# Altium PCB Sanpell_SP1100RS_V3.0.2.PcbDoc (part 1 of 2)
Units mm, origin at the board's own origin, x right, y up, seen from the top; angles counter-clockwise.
Board outline 126.12 x 87.13 mm, 4 copper layers (TopLayer, GND, PWR, BottomLayer); 152 components, 95 nets, 511 pads, 171 vias.
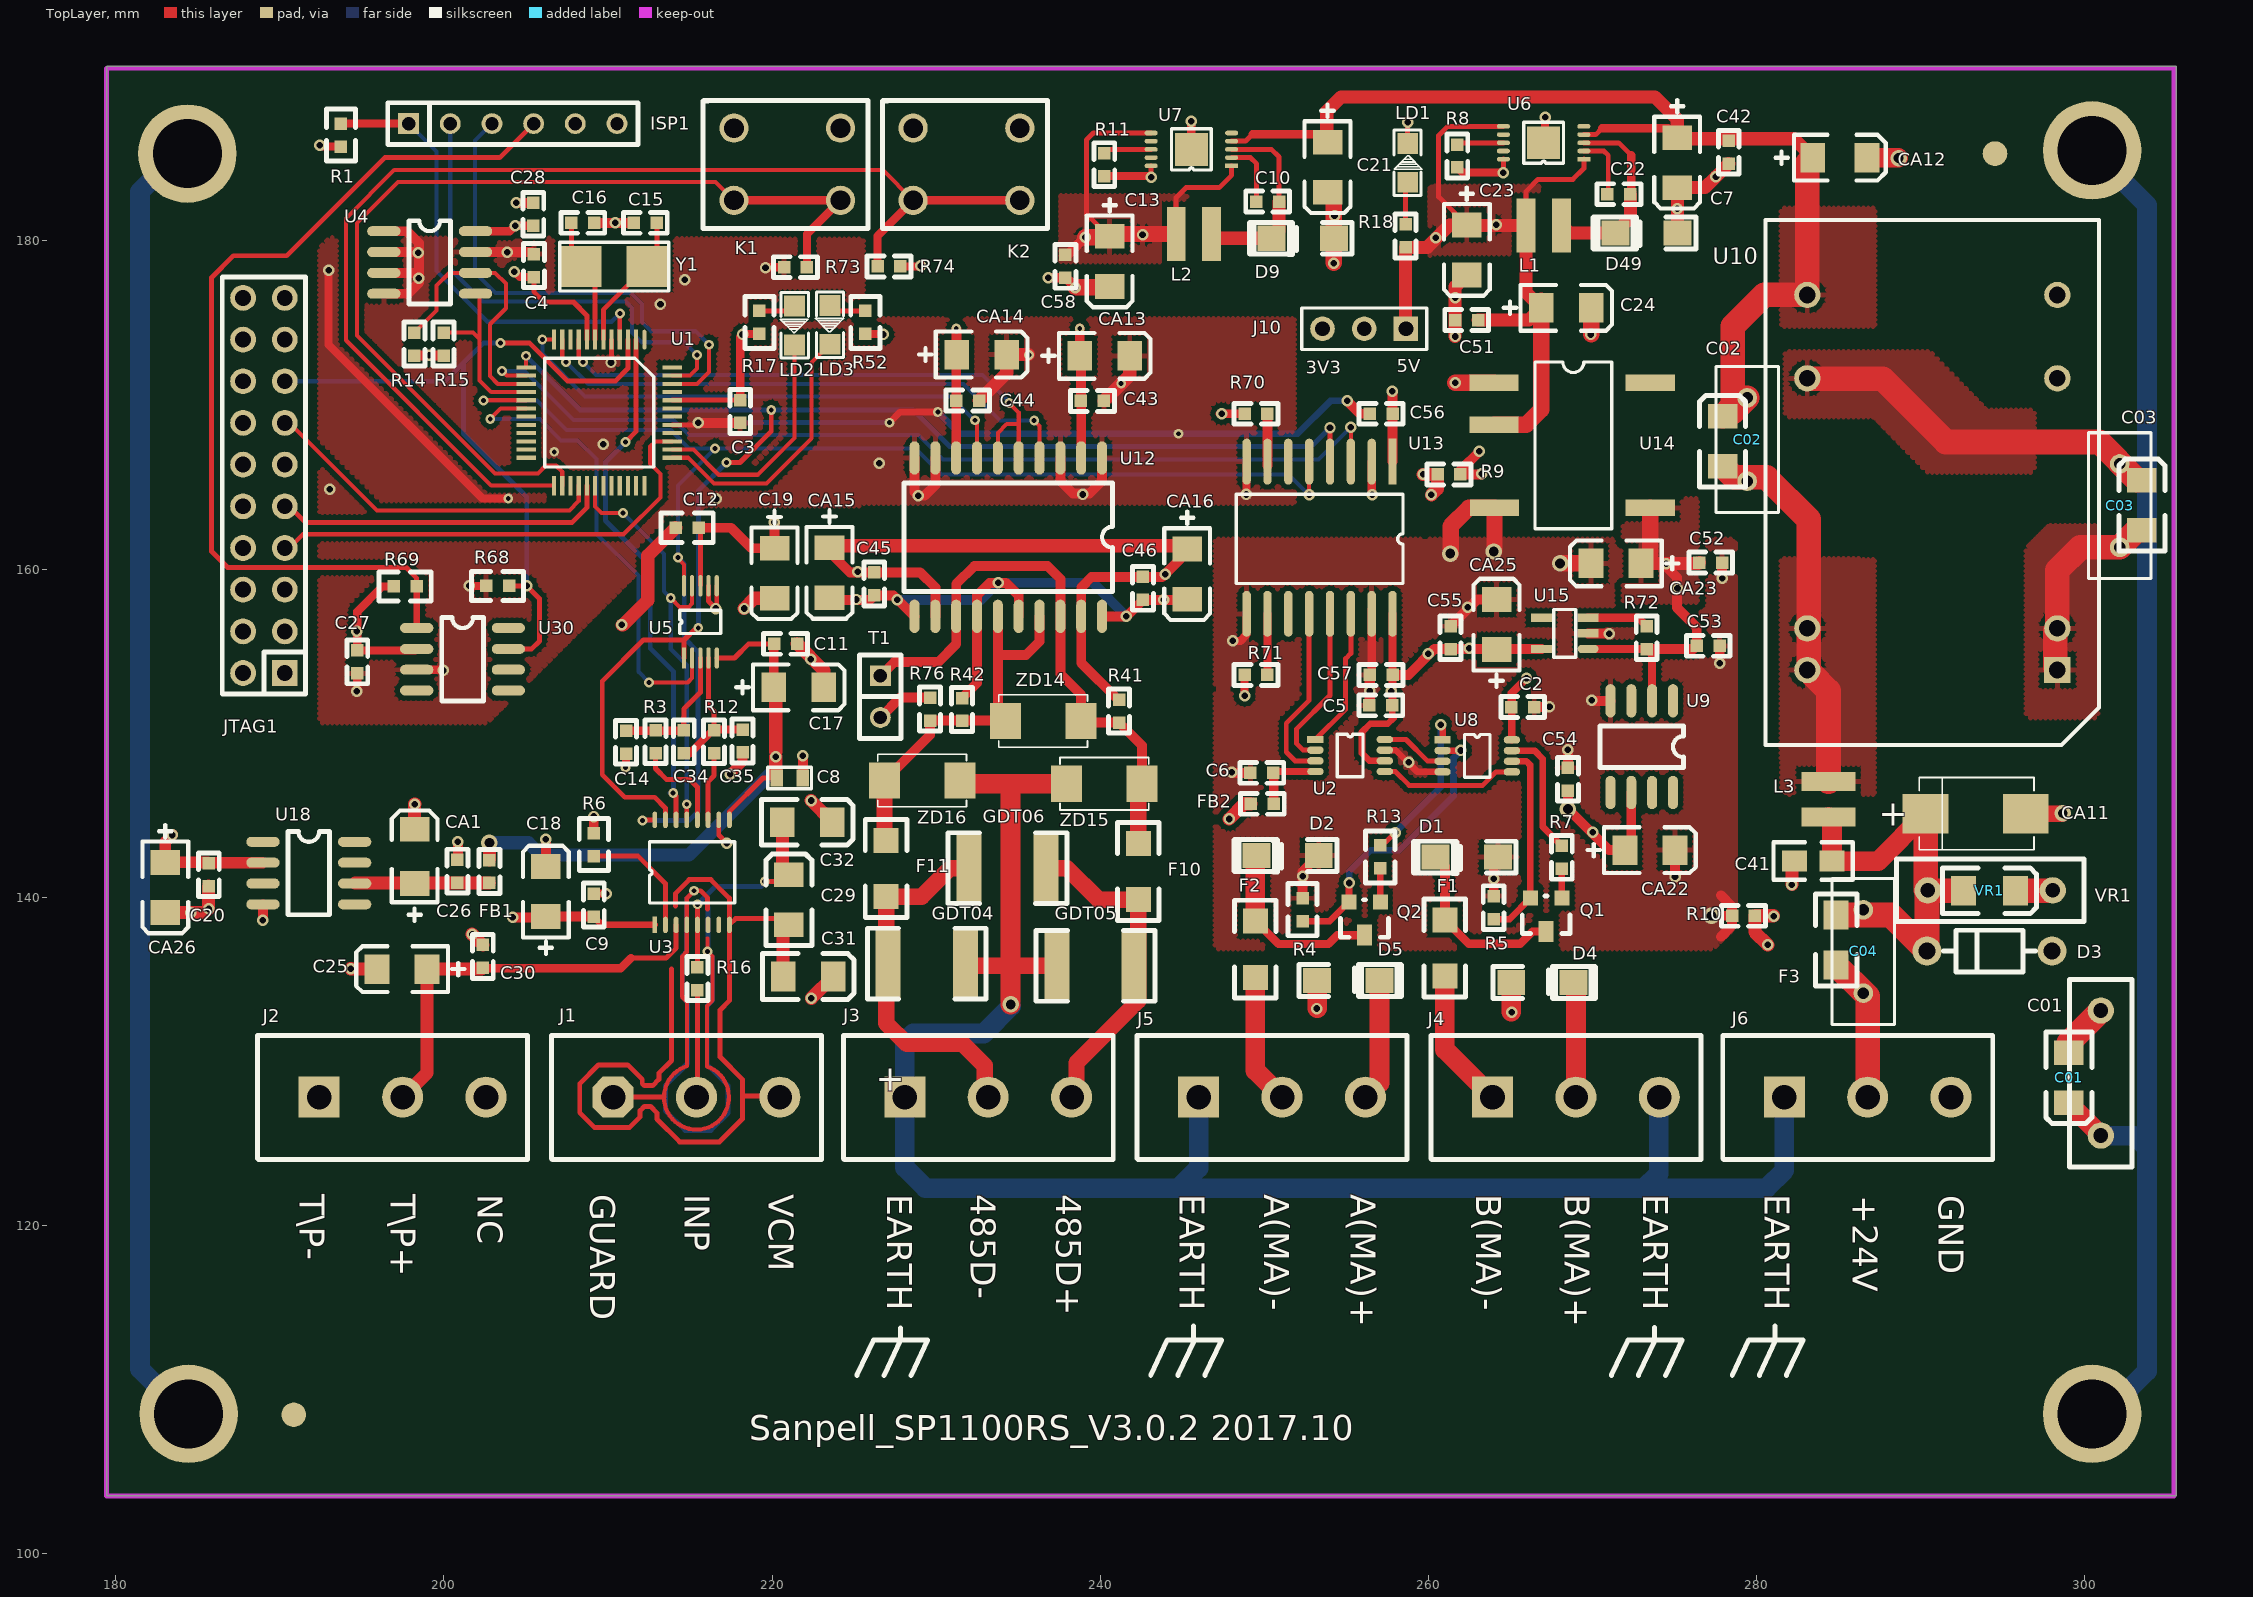
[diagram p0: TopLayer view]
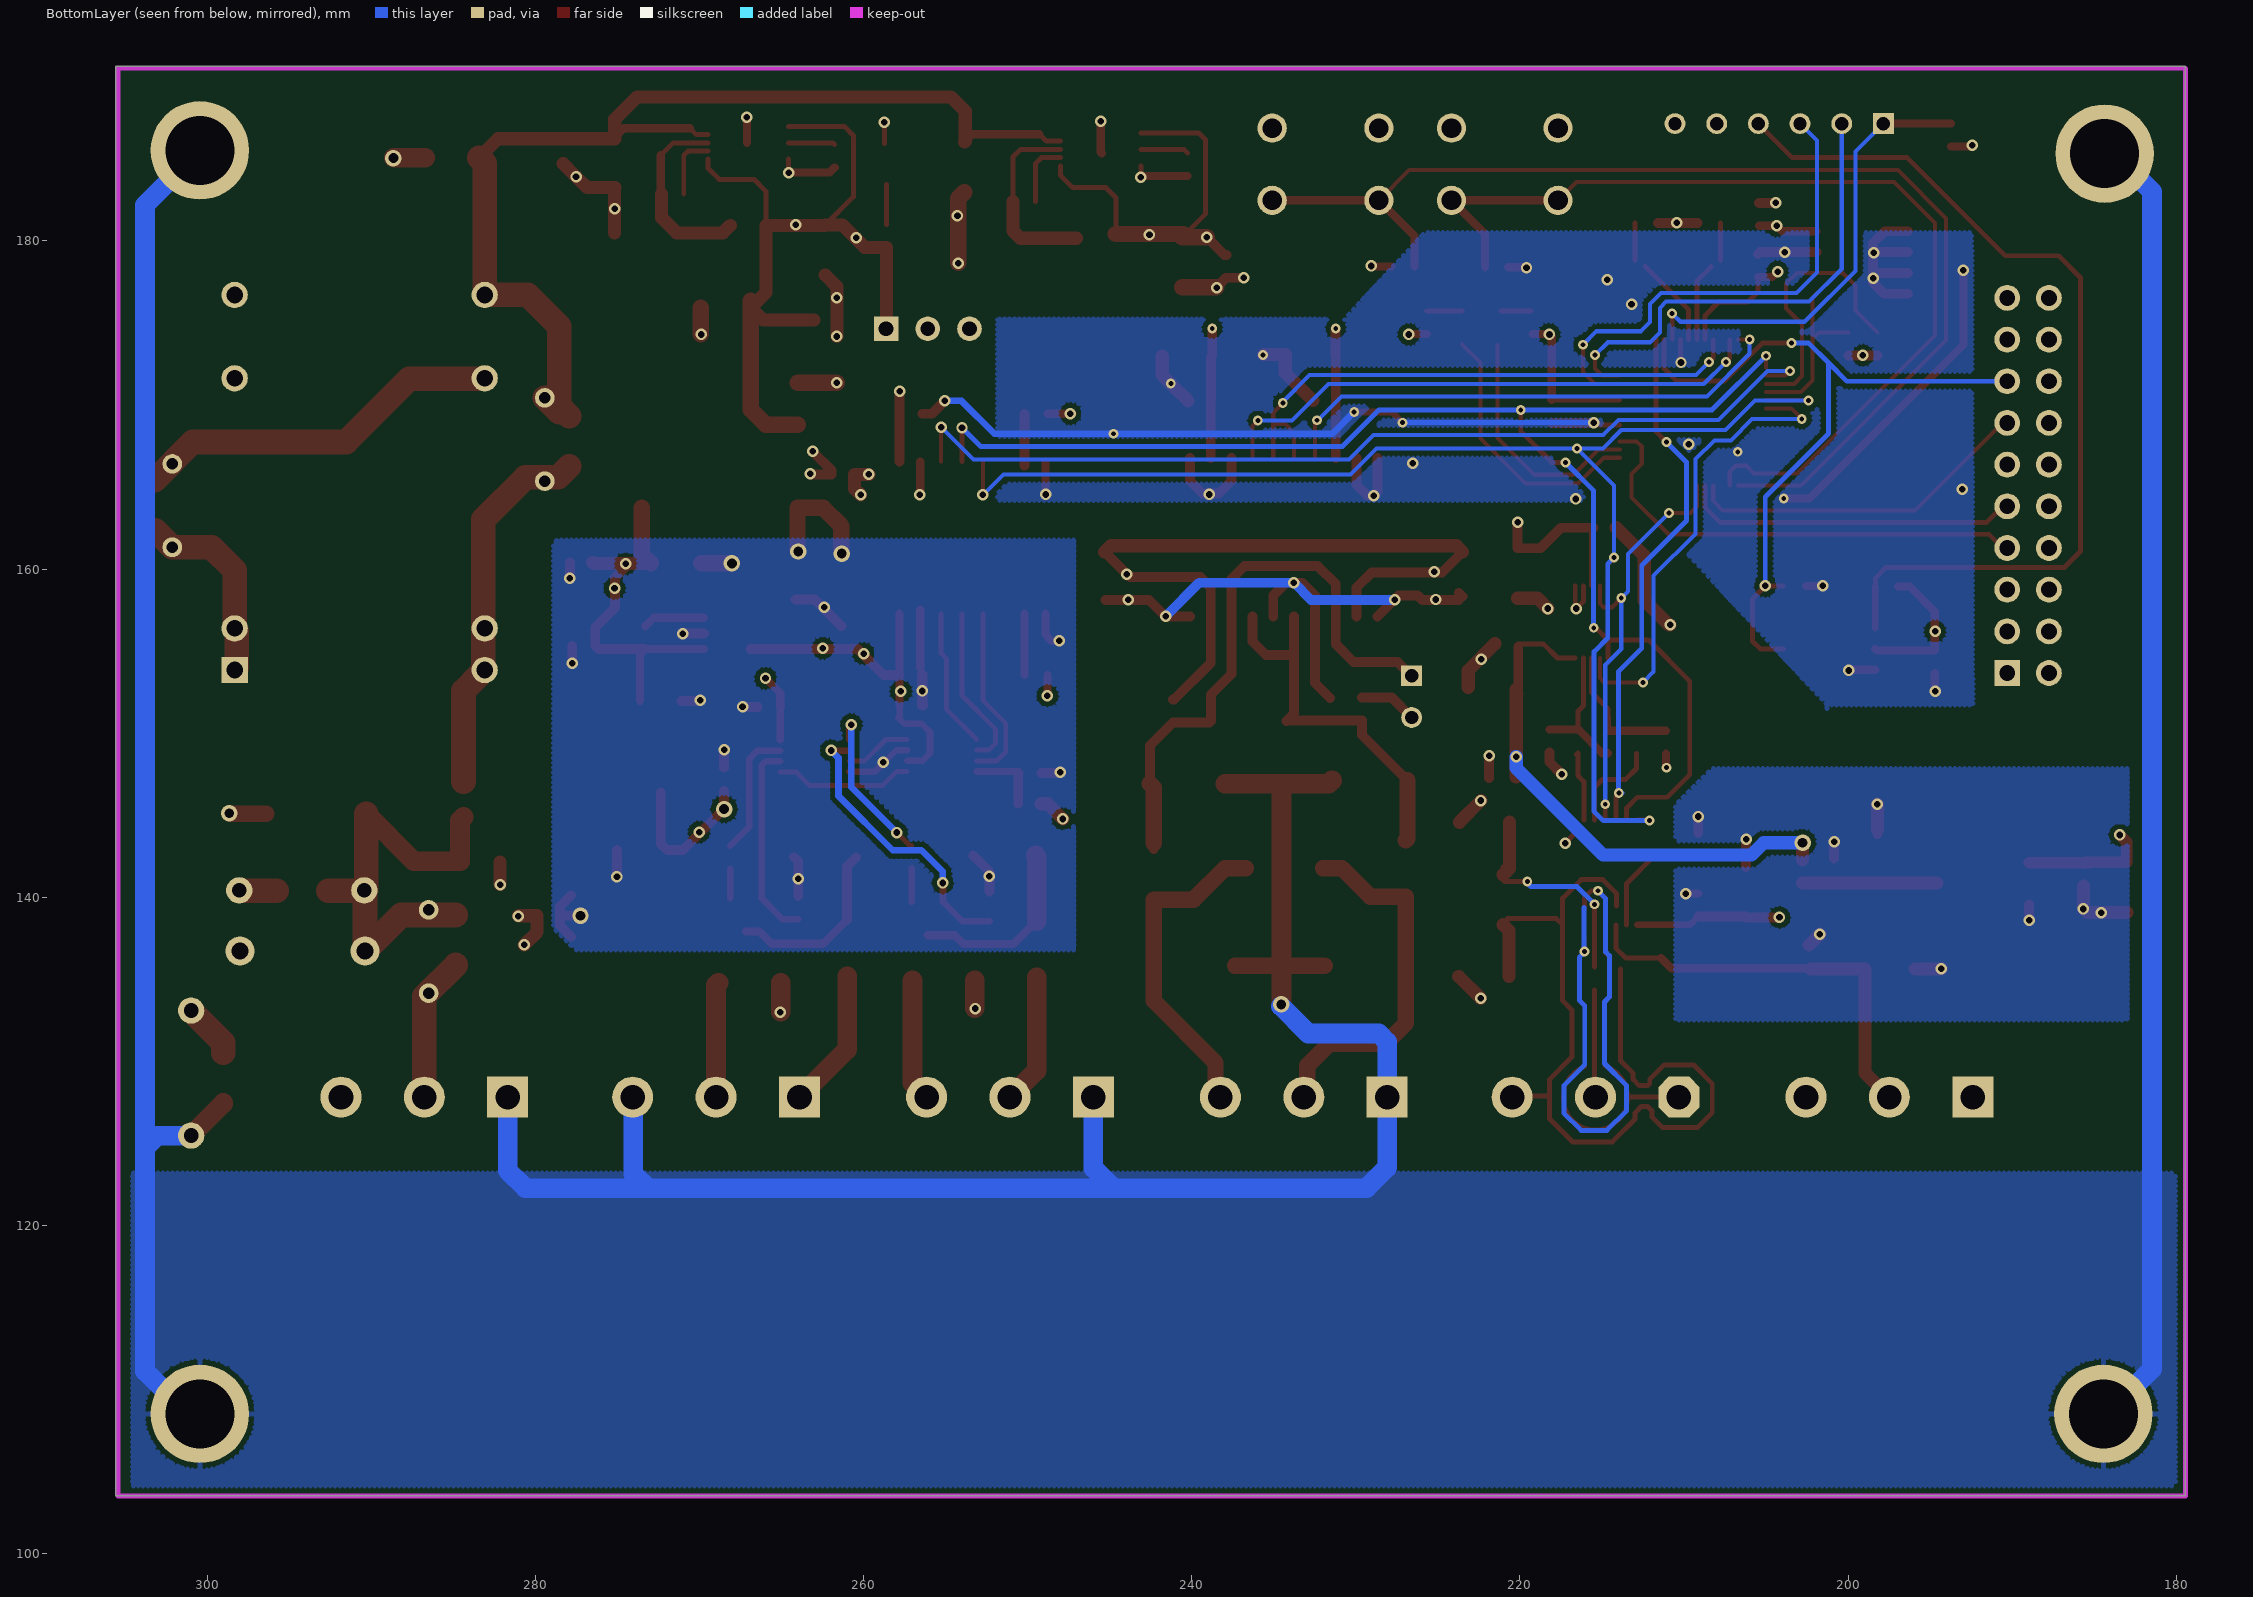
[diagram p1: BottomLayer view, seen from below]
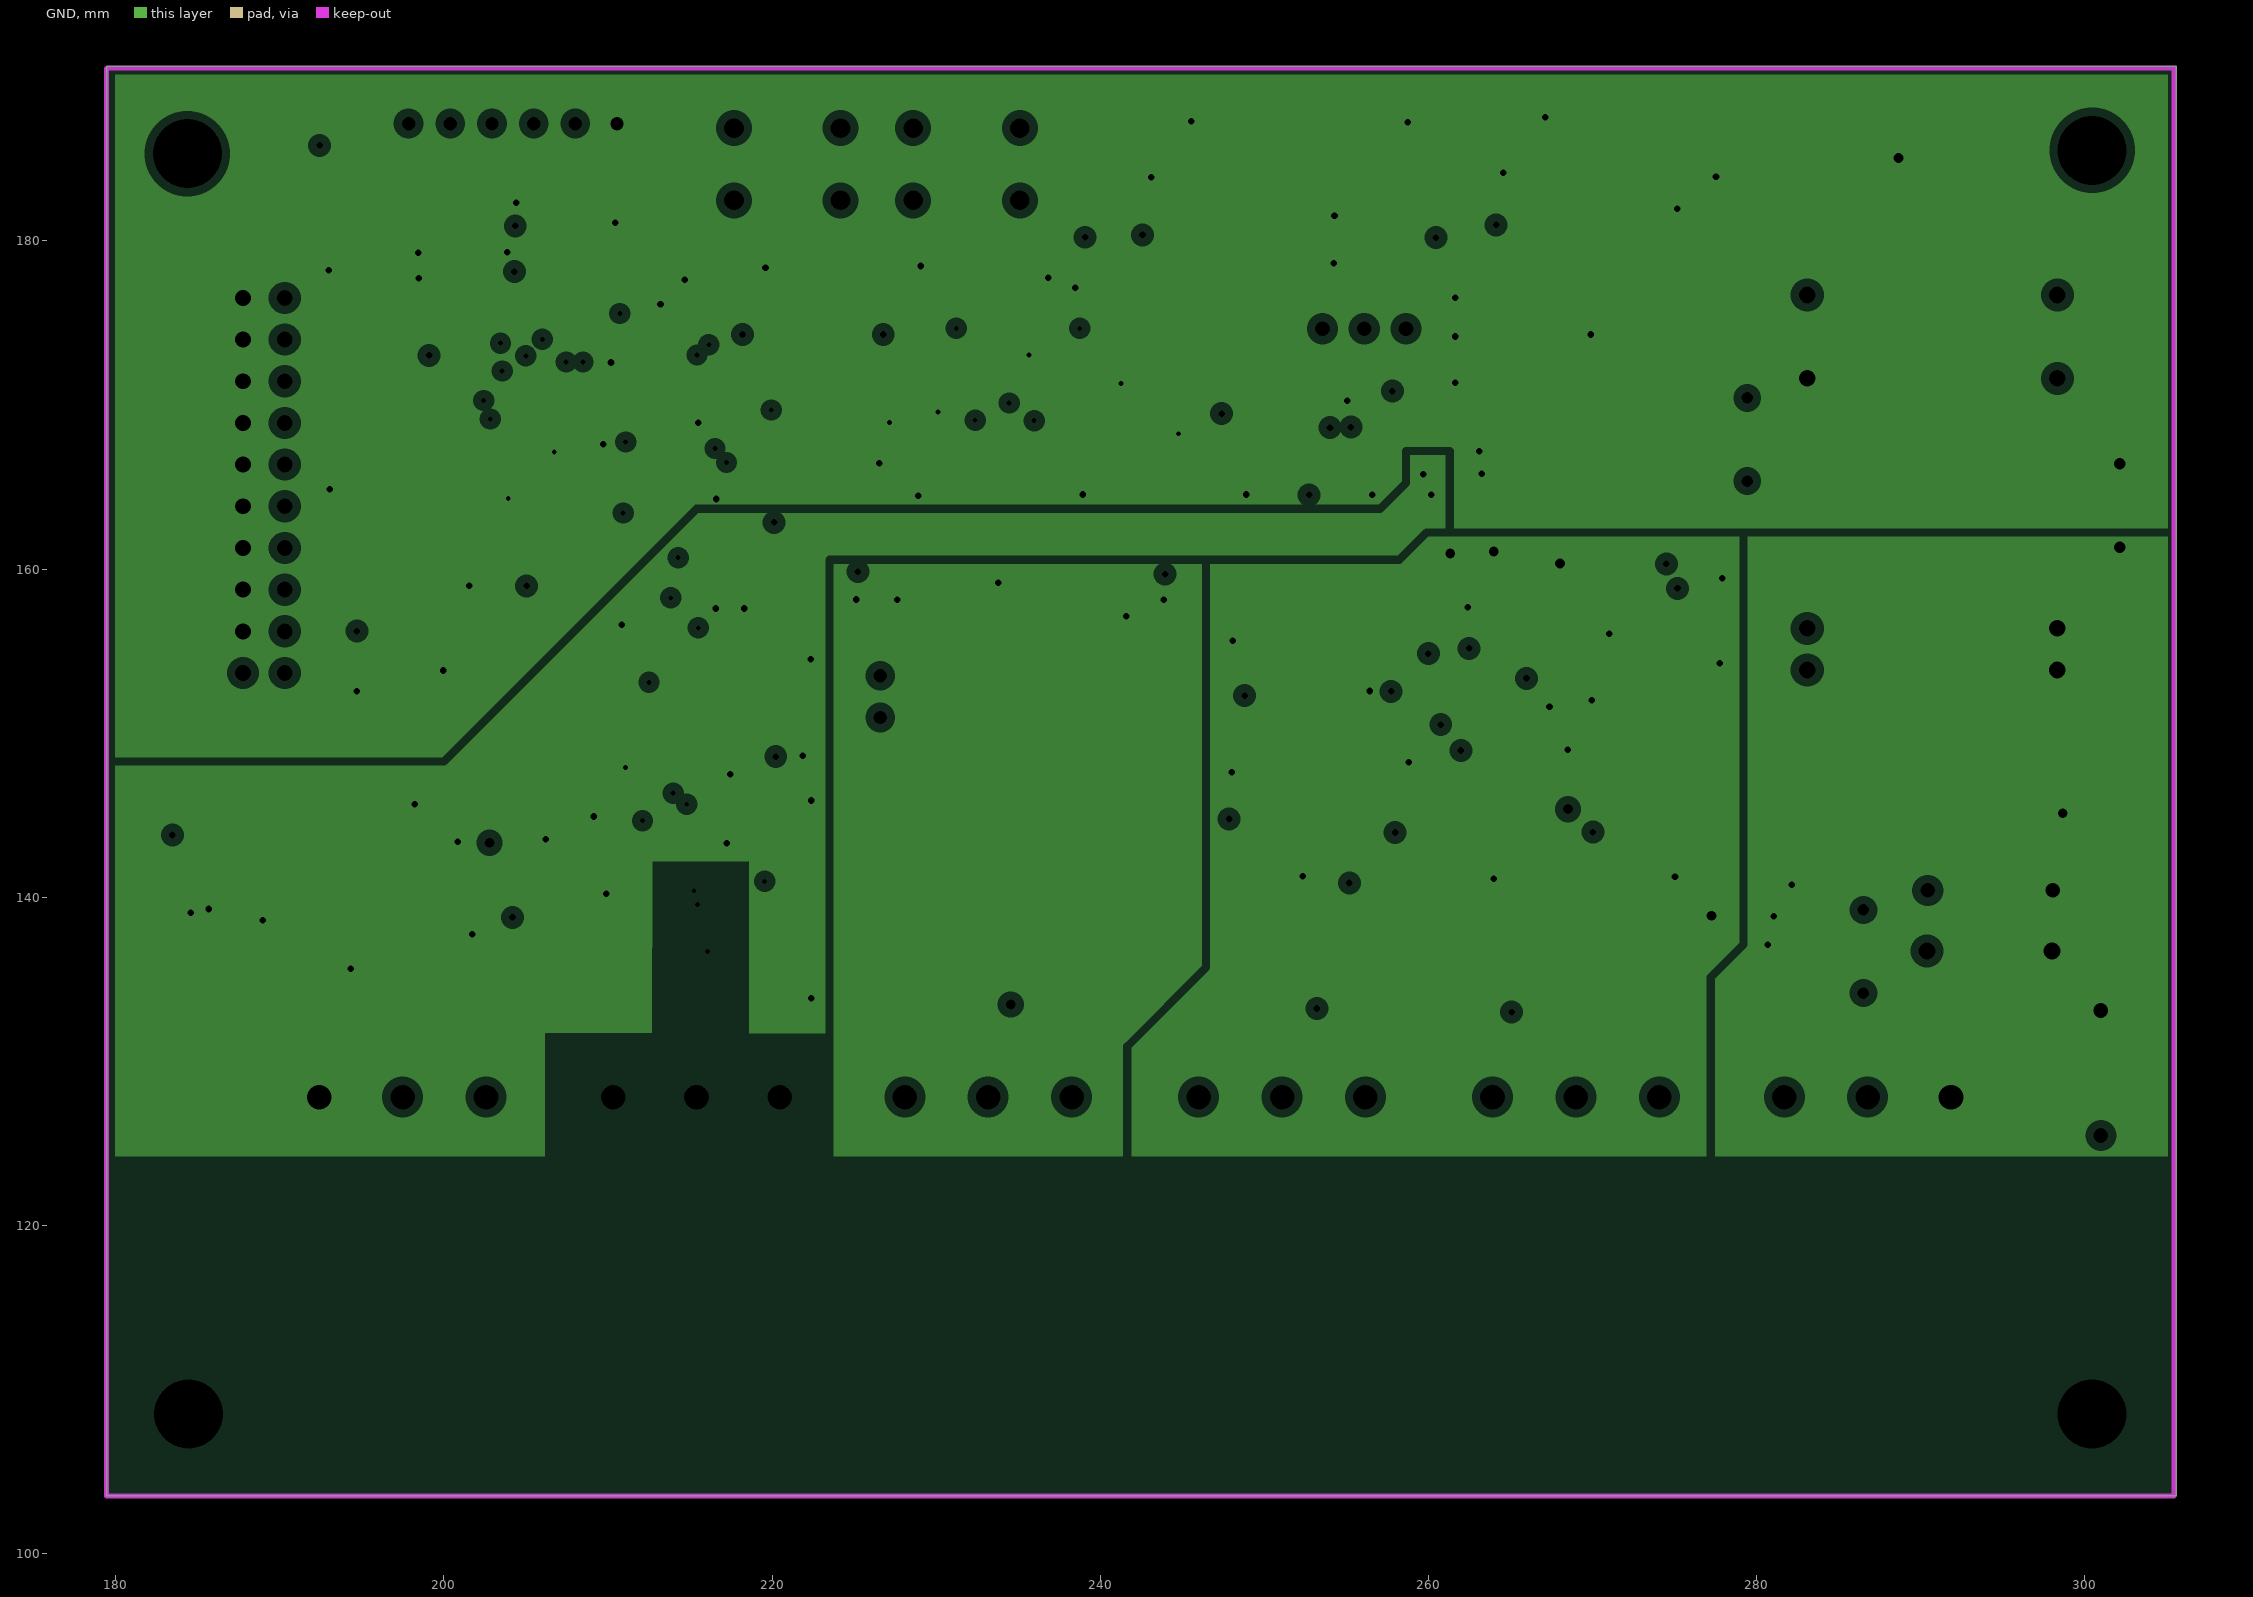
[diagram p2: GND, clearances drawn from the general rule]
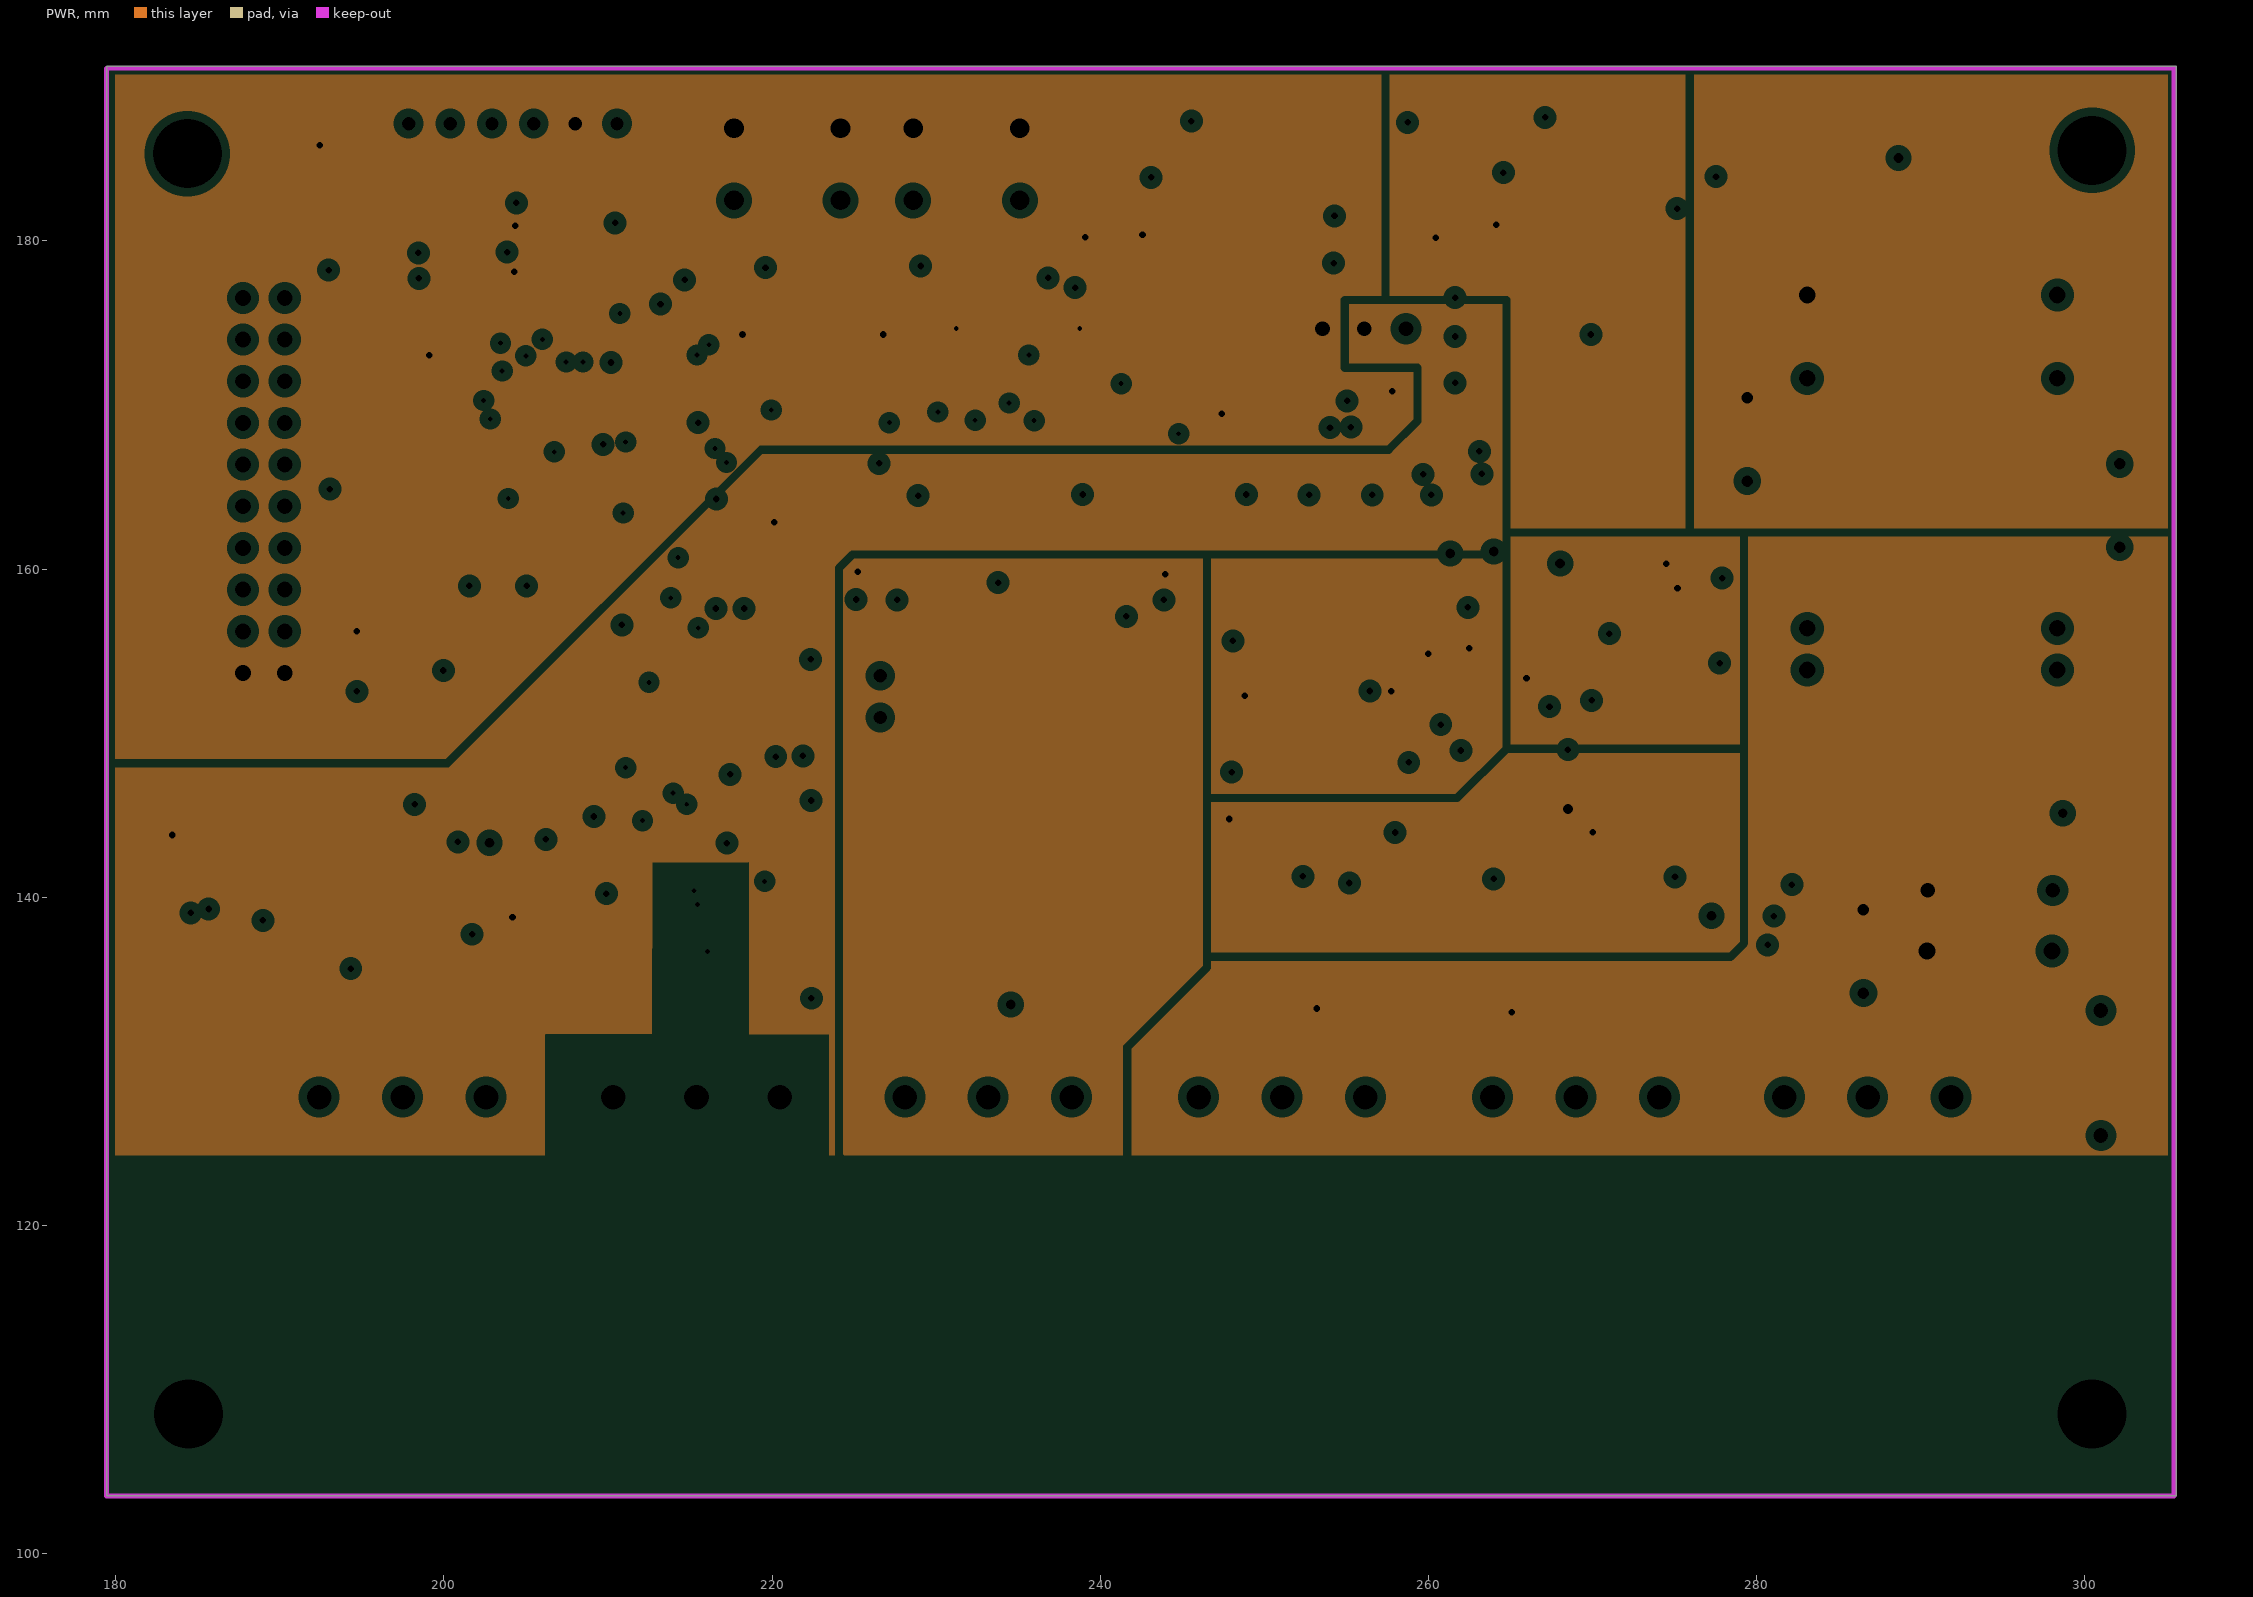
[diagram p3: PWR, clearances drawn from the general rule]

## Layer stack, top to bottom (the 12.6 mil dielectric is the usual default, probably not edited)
TopLayer: signal copper 0.0356
Dielectric: core 0.32, FR-4, Dk 4.8
GND: plane copper 0.0356, net (Multiple Nets)
Dielectric: prepreg 0.32, FR-4, Dk 4.8
PWR: plane copper 0.0356, net (Multiple Nets)
Dielectric: core 0.32, FR-4, Dk 4.8
BottomLayer: signal copper 0.0356

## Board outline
179.45,103.522 305.569,103.522 305.569,190.649 179.45,190.649

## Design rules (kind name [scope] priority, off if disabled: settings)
Clearance Clearance_poly [InPolygon] p1: gap=0.3
Clearance [All] p2: gap=0.15
ComponentClearance [All] p1: gap=0.15 collisioncheckmode=3 verticalgap=0.254 showdistances=FALSE
FabricationTestPointUsage TestPointUsage [All] p1: valid=0 allowmultiple=FALSE
FabricationTestpoint Testpoint [All] p1: side=3 testpointundercomponent=TRUE minsize=1.016 maxsize=2.54 preferedsize=1.524 minholesize=0.508 maxholesize=1.016 preferedholesize=0.813 testpointgrid=0.025 allowsidetop=TRUE allowsidebottom=TRUE usegrid=TRUE gridtolerance=0
HoleSize [All] p1: absolutevalues=TRUE maxlimit=5.08 minlimit=0.025 maxpercent=80.000 minpercent=20.000
MinimumSolderMaskSliver [All] p1: minsoldermaskwidth=0.15
PlaneClearance [All] p1: clearance=0.5
PlaneConnect [All] p1: planeconnectstyle=Relief reliefexpansion=0.5 reliefentries=4 reliefconductorwidth=0.3 reliefairgap=0.3
PolygonConnect PolygonConnect_via [IsVia] p1: connectstyle=Direct reliefconductorwidth=0.254 reliefentries=4 polygonreliefangle="90 Angle"
PolygonConnect [All] p2: connectstyle=Relief reliefconductorwidth=0.3 reliefentries=4 polygonreliefangle="90 Angle"
RoutingVias [All] p1: holewidth=0.305 width=0.61 viastyle="Through Hole" minholewidth=0.254 minwidth=0.508 maxholewidth=2 maxwidth=5
SilkToSilkClearance [All] p1: silktosilkclearance=0
SilkscreenOverComponentPads [All] p1: minsilkscreentomaskgap=0
SolderMaskExpansion [All] p1: expansion=0.102
Width [All] p1: maxlimit=5.08 minlimit=0.2 preferedwidth=0.254
19 further rules are at their usual default settings.

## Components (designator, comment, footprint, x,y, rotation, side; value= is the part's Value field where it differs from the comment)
C01 "1nF/2KV" RAD0.3 300.975,133.1 r270 top
C01 "1nF/2kV" 1206#1 299.025,127.475 r270 top
C02 "1nF/2KV" RAD-0.2 279.424,167.9 r90 top
C2 "0.1uF" 0603#1 265.049,151.593 r0 top
C02 "1nF/2kV" 1206#1 277.925,169.325 r90 top
C03 "1nF/2KV" RAD-0.2 302.125,163.875 r90 top
C3 "0.1uF" 0603#1 218.059,170.307 r270 top
C03 "1nF/2kV" 1206#1 303.475,165.427 r90 top
C04 "1nF/2KV" RAD-0.2 286.5,136.7 r90 top
C4 "0.1uF" 0603#1 205.486,177.8 r90 top
C5 "0.1uF" 0603#1 257.8,151.7 r180 top
C6 "0.1uF" 0603#1 250.548,147.587 r180 top
C7 "4.7uF" 1206C#1 275.16,186.3 r270 top
C8 "0.1uF" 0603A 220.275,147.275 r180 top
C9 "0.1uF" 0603#1 209.137,138.829 r90 top
C10 "0.47uF" 0603#1 249.5,182.4 r0 top
C11 "0.1uF" 0603#1 220.125,155.45 r0 top
C12 "0.1uF" 0603#1 215.525,162.525 r180 top
C13 "22uF" 1206C#1 240.575,180.275 r270 top
C14 "0.1uF" 0603#1 211.1,148.75 r90 top
C15 "22pF" 0603#1 212.979,181.102 r180 top
C16 "22pF" 0603#1 207.772,181.102 r0 top
C17 "10uF" 1206C#1 220.1,152.8 r0 top
C18 "10uF" 1206C#1 206.216,138.829 r90 top
C19 "10uF" 1206C#1 220.15,161.275 r270 top
C20 "0.1uF" 0603#1 185.675,142.075 r270 top
C21 "4.7uF" 1206C#1 253.85,186.025 r270 top
C22 "0.47uF" 0603#1 270.91,182.85 r0 top
C23 "22uF" 1206C#1 262.335,180.975 r270 top
C24 "22uF" 1206C#1 266.875,175.925 r0 top
C25 "10uF" 1206C#1 198.975,135.625 r180 top
C26 "0.1uF" 0603#1 200.825,140.9 r90 top
C27 "0.1uF" 0603#1 194.725,155.05 r270 top
C28 "0.1uF" 0603#1 205.45,180.925 r90 top
C29 "10uF" 1206#1 221.025,141.375 r90 top
C30 "0.1uF" 0603#1 202.375,135.7 r90 top
C31 "10uF" 1206#1 223.725,135.175 r0 top
C32 "10uF" 1206#1 223.675,144.575 r0 top
C34 "0.1uF" 0603#1 214.625,150.175 r270 top
C35 "0.1uF" 0603#1 218.2,150.225 r270 top
C41 "1uF/50V" 0805 284.6,142.225 r180 top
C42 "0.1uF" 0603#1 278.3,186.1 r270 top
C43 "0.1uF" 0603#1 238.825,170.25 r0 top
C44 "0.1uF" 0603#1 231.225,170.275 r0 top
C45 "0.1uF" 0603#1 226.225,159.797 r270 top
C46 "0.1uF" 0603#1 242.6,158.128 r90 top
C51 "0.1uF" 0603#1 263.025,175.175 r180 top
C52 "0.1uF" 0603#1 276.5,160.4 r0 top
C53 "0.1uF" 0603#1 276.35,155.325 r0 top
C54 "0.1uF" 0603#1 268.5,146.5 r90 top
C55 "0.1uF" 0603#1 261.35,155.125 r90 top
C56 "0.1uF" 0603#1 257.81,169.471 r180 top
C57 "0.1uF" 0603#1 257.81,153.556 r180 top
C58 "0.1uF" 0603#1 237.875,179.15 r270 top
CA1 "10uF" 1206C#2 198.216,140.843 r90 top
CA11 "100uF/50V" D 290.3,145.1 r0 top
CA12 "10uF/50V" 1206C#2 283.425,185.075 r0 top
CA13 "10uF" 1206C#1 238.75,173 r0 top
CA14 "10uF" 1206C#1 231.25,173.075 r0 top
CA15 "10uF" 1206C#1 223.5,161.3 r270 top
CA16 "10uF" 1206C#1 245.3,161.225 r270 top
CA22 "10uF" 1206C#1 271.975,142.875 r0 top
CA23 "10uF" 1206C#1 272.95,160.35 r180 top
CA25 "10uF" 1206C#1 264.15,155.1 r90 top
CA26 "10uF" 1206C#1 183.025,142.125 r270 top
D1 "SMF26AG" 1206D 264.05,142.45 r180 top
D2 "SMF26AG" 1206D 253.125,142.55 r180 top
D3 "1N4007" 1N4007 298,136.725 r180 top
D4 "CD1607-B140" 1206D 265.233,134.8 r0 top
D5 "CD1607-B140" 1206D 253.408,134.925 r0 top
D9 "CD1607-B140" 1206D 254.05,180.167 r180 top
D49 "CD1607-B140" 1206D 274.996,180.49 r180 top
F1 "1210L005WR" 1206#2 261,138.625 r270 top
F2 "1210L005WR" 1206#2 249.45,138.554 r270 top
F3 "1210L005WR" 1206#3 284.85,135.875 r90 top
F10 "FUSE1" 1206#2 242.316,143.29 r270 top
F11 "FUSE1" 1206#2 226.949,143.475 r270 top
FB1 "BLM18PG600SN1" 0603#1 202.775,140.875 r90 top
FB2 "BLM18PG600SN1" 0603#1 250.575,145.7 r180 top
GDT04 "10uF" 1812 227.076,135.955 r0 top
GDT05 "10uF" 1812 237.363,135.828 r0 top
GDT06 "10uF" 1812 232.001,141.775 r0 top
ISP1 "ISP" SIP6 197.85,187.15 r0 top
J1 "" PH3-S#1 210.312,127.823 r0 top
J2 "" PH3-S#2 192.405,127.823 r0 top
J3 "CON2" PH3-S#2 228.092,127.823 r0 top
J4 "" PH3-S#2 263.906,127.823 r0 top
J5 "" PH3-S#2 245.999,127.823 r0 top
J6 "CON3" PH3-S#2 281.686,127.823 r0 top
J10 "Comment" HDR1X3 258.625,174.65 r180 top
JTAG1 "DEBUG" IDC20 190.306,153.67 r90 top
K1 "SW_PB4" "SW-PB ANJIAN" 220.926,184.675 r0 top
K2 "SW_PB4" "SW-PB ANJIAN" 231.848,184.675 r0 top
L1 "LPS3010-472ML" LPS3010 268.11,180.95 r180 top
L2 "LPS3010-472ML" LPS3010 246.784,180.421 r180 top
L3 "4.7uH" LPS3010 284.375,144.9 r90 top
LD1 "PWR" 0603#2 258.734,183.545 r90 top
LD2 "PWR" 0603#2 221.366,176.063 r270 top
LD3 "PWR" 0603#2 223.523,176.102 r270 top
Q1 "MMBT3904" SOT-23 268.13,139.952 r180 top
Q2 "MMBT3904" SOT-23 257.063,139.727 r180 top
R1 "10K" 0603#1 193.725,187.15 r270 top
R3 "1K" 0603#1 212.9,150.175 r270 top
R4 "100R 1%" 0603#1 252.325,138.55 r90 top
R5 "100R 1%" 0603#1 263.975,138.675 r90 top
R6 "1K" 0603#1 209.137,142.512 r90 top
R7 "10K" 0603#1 268.13,143.135 r270 top
R8 "49.9K" 0603#1 261.76,185.875 r270 top
R9 "0R" 0603#1 261.95,165.775 r180 top
R10 "0R" 0603#1 278.5,138.875 r0 top
R11 "49.9K" 0603#1 240.25,185.35 r270 top
R12 "1K" 0603#1 216.462,150.181 r270 top
R13 "10K" 0603#1 257.063,143.162 r270 top
R14 "10K" 0603#1 198.206,174.416 r270 top
R15 "10K" 0603#1 199.984,174.416 r270 top
R16 "1K" 0603#1 215.45,135.75 r270 top
R17 "1K" 0603#1 219.234,175.734 r270 top
R18 "1K" 0603#1 258.607,181.005 r270 top
R41 "47K" 0603#1 241.15,152.05 r270 top
R42 "47K" 0603#1 231.575,150.75 r90 top
R52 "1K" 0603#1 225.682,175.734 r270 top
R68 "10K" 0603#1 202.575,158.975 r0 top
R69 "10K" 0603#1 196.947,158.944 r0 top
R70 "4K7" 0603#1 248.793,169.471 r0 top
R71 "4K7" 0603#1 250.19,153.556 r180 top
R72 "4.7k" 0603#1 273.3,155.125 r90 top
R73 "10K" 0603#1 220.728,178.4 r0 top
R74 "10K" 0603#1 227.825,178.45 r180 top
R76 "120" 0603#1 229.625,150.775 r90 top
T1 "2*2.54" SIP2 226.6,153.5 r270 top
U1 "LPC1316FBD48" 0603#3 212.217,173.99 r270 top locked
U2 "LT2602" 0603#4 253.111,149.619 r0 top
U3 "LMP91200" 0603#5 212.852,138.321 r90 top
U4 "AT24C64D" SO-8 196.342,180.594 r0 top
U5 "AD7788" AD7788BRM 214.63,154.587 r90 top
U6 "LT3971-5" 0603#6 269.468,184.981 r180 top
U7 "LT3971-3.3" 0603#6 248.002,184.579 r180 top
U8 "AD8646" 0603#4 260.858,149.594 r0 top
U9 "ADR03" SO-8 274.9,151.975 r270 top
U10 "URB2424ZP-6WR3" URB2424ZP-6WR3 298.325,153.85 r90 top
U12 "ADM2587E" SOL-20 240.11,166.775 r270 top
U13 "ADUM1401" ADUM1401 257.81,166.55 r270 top
U14 "B0505XT-1W" B0505XT-1W 264,171.35 r0 top
U15 "TPS76033DBVR" SOT23-5A 269.725,155.15 r90 top
U18 "ADR03" SO-8 188.976,143.383 r0 top
U30 "MAX708S" SO-8 198.346,156.41 r0 top
VR1 "14D560" 1206#4 295.65,140.4 r0 top
VR1 "14D560" RAD0.3 290.425,140.425 r0 top
Y1 "12MHz" CY5.4X4.6 212.344,178.435 r180 top
ZD14 "SMBJ12" ZD 238.825,150.75 r180 top
ZD15 "SMBJ12" ZD 242.55,146.925 r180 top
ZD16 "SMBJ12" ZD 231.45,147.125 r180 top

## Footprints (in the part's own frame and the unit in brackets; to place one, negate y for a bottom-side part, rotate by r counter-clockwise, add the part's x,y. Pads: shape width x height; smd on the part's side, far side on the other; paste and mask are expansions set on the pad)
1N4007 [mil]
  round 70 hole 40: A(0,0) K(300,0)
  silkscreen extent 40,-50 260,50
0603#1 [mil]
  rect 30x30 smd: 1(0,0) 2(55,0)
  silkscreen extent -25,-25 80,25
0603#2 [mil]
  rect 50x50 smd: A(1.18,0) K(94.49,0)
  silkscreen extent -31,-34 126,33
0603#3 [mil]
  oval 47.24x9.84 smd: 1(0,0)
  rect 47.24x9.84 smd: 2(0,-19.68) 3(0,-39.37) 4(0,-59.06) 5(0,-78.74) 6(0,-98.42) 7(0,-118.11) 8(0,-137.8) 9(0,-157.48) 10(0,-177.16) 11(0,-196.85) 12(0,-216.53) 25(350.39,-216.53) 26(350.39,-196.85) 27(350.39,-177.16) 28(350.39,-157.48) 29(350.39,-137.8) 30(350.39,-118.11) 31(350.39,-98.42) 32(350.39,-78.74) 33(350.39,-59.06) 34(350.39,-39.37) 35(350.39,-19.68) 36(350.39,0)
  rect 9.84x47.24 smd: 13(66.93,-283.46) 14(86.61,-283.46) 15(106.3,-283.46) 16(125.98,-283.46) 17(145.67,-283.46) 18(165.35,-283.46) 19(185.04,-283.46) 20(204.72,-283.46) 21(224.41,-283.46) 22(244.09,-283.46) 23(263.78,-283.46) 24(283.46,-283.46) 37(283.46,66.93) 38(263.78,66.93) 39(244.09,66.93) 40(224.41,66.93) 41(204.72,66.93) 42(185.04,66.93) 43(165.35,66.93) 44(145.67,66.93) 45(125.98,66.93) 46(106.3,66.93) 47(86.61,66.93) 48(66.93,66.93)
  silkscreen extent 45,-239 306,22
0603#4 [mil]
  rect 39.37x17.72 smd: 1(0,0)
  oval 39.37x17.72 smd: 2(0,-25.59) 3(0,-51.18) 4(0,-76.77) 5(166.54,-76.77) 6(166.54,-51.18) 7(166.54,-25.59) 8(166.54,0)
  silkscreen extent 53,-90 114,13
0603#5 [mil]
  rect 39.37x11.81 smd: 1(0,0)
  oval 39.37x11.81 smd: 2(0,-25.59) 3(0,-51.18) 4(0,-76.77) 5(0,-102.36) 6(0,-127.95) 7(0,-153.54) 8(0,-179.13) 9(251.97,-179.13) 10(251.97,-153.54) 11(251.97,-127.95) 12(251.97,-102.36) 13(251.97,-76.77) 14(251.97,-51.18) 15(251.97,-25.59) 16(251.97,0)
  silkscreen extent 53,-192 199,13
0603#6 [mil]
  rect 31.5x11.02 smd: 1(0,0)
  oval 31.5x11.02 smd: 2(0,-19.69) 3(0,-39.37) 4(0,-59.06) 5(0,-78.74) 6(192.91,-78.74) 7(192.91,-59.06) 8(192.91,-39.37) 9(192.91,-19.69) 10(192.91,0)
  rect 78.74x78.74 smd: 11(96.46,-39.37)
  silkscreen extent 49,-89 144,10
0603A [mil]
  rect 30x40 smd: 1(0,0) 2(-63,0)
  silkscreen extent -84,-26 21,26
0805 [mil]
  rect 60x50 smd: 1(0.39,0.31) 2(90.39,0.31)
  silkscreen extent -50,-45 140,45
1206#1 [mm]
  rect 1.5x1.8 smd: 1(-3.048,0) 2(0,0)
  silkscreen extent -4.32,-1.4 1.27,1.4
1206#2 [mm]
  rect 1.524x1.524 smd: 1(0,0) 2(3.429,0)
  silkscreen extent -1.27,-1.27 4.7,1.27
1206#3 [mm]
  rect 1.778x1.524 smd: 1(0,0) 2(3.048,0)
  silkscreen extent -1.27,-1.27 4.32,1.27
1206#4 [mm]
  rect 1.5x1.8 smd: 1(-3.048,0) 2(0.127,0)
  silkscreen extent -4.32,-1.4 1.4,1.4
1206C#1 [mm]
  rect 1.5x1.8 smd: 1(0,0) 2(3.048,0)
  silkscreen extent -2.29,-1.4 4.32,1.4
1206C#2 [mm]
  rect 1.5x1.8 smd: 1(0,0) 2(3.302,0)
  silkscreen extent -2.29,-1.4 4.44,1.4
1206D [mm]
  rect 1.7x1.524 smd: 1(-0.19,0.003) 2(3.61,0.003)
  silkscreen extent -1.3,-0.97 4.96,0.99
1812 [mil]
  rect 60x164.37 smd: 1(0,0) 2(185,0)
  silkscreen extent -50,-85 235,85
AD7788BRM [mm]
  rect 1.3x0.25 smd: 1(0,0)
  oval 1.3x0.25 smd: 2(0,-0.5) 3(0,-1) 4(0,-1.5) 5(0,-2) 6(4.4,-2) 7(4.4,-1.5) 8(4.4,-1) 9(4.4,-0.5) 10(4.4,0)
  silkscreen extent 1.48,-2.25 2.92,0.25
ADUM1401 [mm]
  rect 2.8x0.51 smd: 1(0,0)
  oval 2.8x0.51 smd: 2(0,-1.27) 3(0,-2.54) 4(0,-3.81) 5(0,-5.08) 6(0,-6.35) 7(0,-7.62) 8(0,-8.89) 9(9.271,-8.89) 10(9.271,-7.62) 11(9.271,-6.35) 12(9.271,-5.08) 13(9.271,-3.81) 14(9.271,-2.54) 15(9.271,-1.27) 16(9.271,0)
  silkscreen extent 1.99,-9.53 7.43,0.64
B0505XT-1W [mm]
  rect 3x1 smd: 1(0,0) 2(0,-2.54) 4(0.025,-7.62) 5(9.51,-7.62) 8(9.51,0)
  silkscreen extent 2.49,-8.89 7.17,1.27
CY5.4X4.6 [mm]
  rect 2.5x2.5 smd: 1(-0.025,0) 2(4,0)
  silkscreen extent -1.35,-1.49 5.28,1.49
D [mil]
  rect 110x94.49 smd: 1(0,0) 2(240,0)
  silkscreen extent -16,-87 260,87
HDR1X3 [mm] "Connector; Header; 3 Position"
  rect 1.5x1.5 hole 0.9: 1(0,0)
  round 1.5 hole 0.9: 2(2.54,0) 3(5.08,0)
  silkscreen extent -1.27,-1.27 6.35,1.27
IDC20 [mil]
  rect 62x62 hole 38: 1(0,0)
  round 62 hole 38: 2(0,100) 3(100,0) 4(100,100) 5(200,0) 6(200,100) 7(300,0) 8(300,100) 9(400,0) 10(400,100) 11(500,0) 12(500,100) 13(600,0) 14(600,100) 15(700,0) 16(700,100) 17(800,0) 18(800,100) 19(900,0) 20(900,100)
  silkscreen extent -50,-50 950,150
LPS3010 [mm]
  rect 1.14x3.3 smd: 1(0,0) 2(2.16,0)
PH3-S#1 [mm]
  oct 2.5x2.5 hole 1.5: 1(0,0)
  round 2.5 hole 1.5: 2(5.08,0) 3(10.16,0)
  silkscreen extent -3.75,-3.81 12.7,3.75
PH3-S#2 [mm]
  rect 2.5x2.5 hole 1.5: 1(0,0)
  round 2.5 hole 1.5: 2(5.08,0) 3(10.16,0)
  silkscreen extent -3.75,-3.81 12.7,3.75
RAD0.3 [mm]
  round 1.6 hole 0.9: 1(0,0) 2(7.62,0)
  silkscreen extent -1.91,-1.91 9.53,1.91
RAD-0.2 [mm] "Radial Cap, Thru-Hole; 2 Leads; 0.2 in Pin Spacing"
  round 1.2 hole 0.7: 1(-2.54,0) 2(2.54,0)
  silkscreen extent -4.44,-1.91 4.44,1.91
SIP2 [mil]
  rect 50x50 hole 32: 1(0,0)
  round 50 hole 32: 2(100,0)
  silkscreen extent -50,-50 150,50
SIP6 [mil]
  rect 50x50 hole 32: 1(0,0)
  round 50 hole 32: 2(100,0) 3(200,0) 4(300,0) 5(400,0) 6(500,0)
  silkscreen extent -50,-50 550,50
SO-8 [mil]
  oval 80x24 smd: 1(0,0) 2(0,-50) 3(0,-100) 4(0,-150) 5(220,-150) 6(220,-100) 7(220,-50) 8(220,0)
  silkscreen extent 60,-175 160,25
SOL-20 [mil]
  oval 80x24 smd: 1(0,0) 2(0,-50) 3(0,-100) 4(0,-150) 5(0,-200) 6(0,-250) 7(0,-300) 8(0,-350) 9(0,-400) 10(0,-450) 11(380,-450) 12(380,-400) 13(380,-350) 14(380,-300) 15(380,-250) 16(380,-200) 17(380,-150) 18(380,-100) 19(380,-50) 20(380,0)
  silkscreen extent 60,-475 320,25
SOT23-5A [mil]
  oval 20x50 smd: 1(-0.49,-0.18)
  rect 20x50 smd: 2(36.91,-0.18) 3(74.32,-0.18) 4(74.32,112.02) 5(-0.49,112.02)
  silkscreen extent -20,30 94,82
SOT-23 [mil]
  rect 36x36 smd: 1(0,0) 2(75,0)
  rect 36x50 smd: 3(38,80)
  silkscreen extent -20,-5 95,85
"SW-PB ANJIAN" [mm]
  round 1.778 hole 1.2: 1(-3.25,2.2) 2(-3.25,-2.2) 3(3.25,2.2) 4(3.25,-2.2)
  silkscreen extent -5.13,-3.93 4.93,3.9
URB2424ZP-6WR3 [mm] "isolated DC-DC converter, 6W"
  rect 1.6x1.6 hole 1.016: 2(0,0)
  round 1.6 hole 1.016: 3(2.54,0) 9(17.78,0) 11(22.86,0) 14(22.86,15.24) 16(17.78,15.24) 22(2.54,15.24) 23(0,15.24)
  silkscreen extent -4.57,-2.54 27.43,17.78
ZD [mm]
  rect 1.9x2.2 smd: 1(0,0) 2(4.6,0)
  silkscreen extent -0.4,-1.6 5,1.6

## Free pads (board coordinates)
  round 6 hole 4.2: 0(184.37,185.323) 4(300.442,185.522) 6(184.442,108.522) 7(300.442,108.522)
  round 1.5 smd: ""(190.85,108.475) ""(294.525,185.325)

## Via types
v1: diameter 0.7, hole 0.4, TopLayer to BottomLayer, 122 vias
v2: diameter 0.6, hole 0.3, TopLayer to BottomLayer, 40 vias
v3: diameter 1, hole 0.6, TopLayer to BottomLayer, 9 vias

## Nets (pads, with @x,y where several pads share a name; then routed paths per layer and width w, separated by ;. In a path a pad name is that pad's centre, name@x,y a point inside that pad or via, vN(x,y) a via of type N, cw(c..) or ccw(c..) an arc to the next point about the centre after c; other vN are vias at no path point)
24VGND_IN: C01.1 C03.1 C41.2 CA11.2 D3.A J6.3 R10.2 U10.2 U10.3 VR1.2 | length 24.4
  TopLayer w0.8: v1(280.675,137.1) 279.897,137.878 R10.2@279.897,138.875 v1@281.025,138.875 ; v1(282.15,140.775) C41.2@282.15,142.138
  TopLayer w1: CA11.2@296.396,145.1 v3@298.625,145.1
  TopLayer w1.5: VR1.2@295.777,140.4 VR1.2@298.02,140.4 ; U10.2@298.199,154 U10.3@298.199,156.24 ; U10.3@298.325,156.39 298.325,159.925 299.735,161.335 C03.1@302.125,161.335 303.169,162.379 C03.1@303.475,162.379 ; C01.1@299.025,130.523 299.025,131.15 C01.1@300.975,133.1
  other v1: 281.05,138.85
  other v3: 298.65,145.125
+24V: C02.2 C7.1 C21.1 C42.1 CA12.1 U6.4 U7.4 U10.14 | length 75.9
  TopLayer w0.3: U7.4@248.002,186.079 248.854,186.079 249.275,186.5 ; U6.4@269.468,186.481 270.185,186.481 270.574,186.87
  TopLayer w0.5: 249.275,186.5 253.375,186.5 C21.1@253.8,186.075 ; 270.574,186.87 274.59,186.87 C7.1@275.16,186.3
  TopLayer w0.8: C21.1@253.85,186.025 253.8,186.075 253.8,187.9 254.675,188.775 273.8,188.775 275.16,187.415 C7.1@275.16,186.3 275.16,186.225 282.275,186.225 CA12.1@283.425,185.075 283.425,176.725 U10.14@283.41,176.71
  TopLayer w1.5: C02.2@277.925,169.325 C02.2@278.55,169.95 ; C02.2@279.424,170.44 278.55,169.566 C02.2@278.55,169.95 ; CA12.1@283.425,185.075 283.085,184.735 U10.14@283.085,176.71 280.46,176.71 278.55,174.8 C02.2@278.55,169.95
+24V_IN: C04.2 C41.1 CA11.1 D3.K D4.1 D5.1 F3.2 L3.1 VR1.1 | length 30.1
  TopLayer w1.2: v1@253.217,133.242 D5.1@253.217,134.928 ; v1@265.042,133.033 D4.1@265.042,134.803 ; L3.1@284.375,144.9 284.59,144.685 C41.1@284.59,142.217 284.59,142.192 287.392,142.192 CA11.1@290.3,145.1
  TopLayer w1.5: F3.2@284.85,138.923 288.182,138.923 D3.K@290.38,136.725 VR1.1@290.38,140.38 ; VR1.1@290.3,140.425 CA11.1@290.3,145.1 ; VR1.1@290.4,140.4 VR1.1@292.602,140.4
  other v1: 265.075,133 253.2,133.225
A_UART5: F10.2 GDT05.2 GDT06.2 J3.3 | length 20.1
  TopLayer w0.8: J3.3@238.252,127.823 J3.3@238.552,128.123
  TopLayer w1: GDT06.2@236.7,141.775 237.975,141.775 239.889,139.861 F10.2@242.316,139.861 242.316,133.691 238.552,129.927 J3.3@238.552,128.123
AGND: C8.2 C9.2 C11.2 C12.2 C14.1 C17.2 C18.2 C19.2 C20.2 C25.2 C26.2 C30.2 C31.2 C32.2 C35.2 CA1.2 CA26.2 J2.1 R6.2 R9.2 U3.10 U5.6 U5.7 U18.4 | length 41.2
  TopLayer w0.3: U5.7@216.13,158.987 216.13,158.045 v1(216.575,157.6) 216.63,157.655 U5.6@216.63,158.987 ; U3.10@216.752,144.721 216.752,143.798 v1(217.25,143.3)
  TopLayer w0.5: C9.2@209.137,140.226 v1(209.899,140.226) ; v2(211.075,147.9) 211.1,147.925 C14.1@211.1,148.75
  TopLayer w0.6: v1(188.975,138.6) v1(188.975,138.6) U18.4@188.976,139.573 ; CA1.2@198.216,143.843 CA1.2@198.216,144.145 ; C26.2@200.854,142.367 v1(200.854,143.375) ; C18.2@206.216,141.829 C18.2@206.216,141.877 v1(206.216,143.528) ; R6.2@209.137,143.909 v1(209.137,144.925) ; v1(217.45,147.5) 218.2,148.25 C35.2@218.2,148.828 ; C8.2@221.875,147.275 v1(221.875,148.625)
  TopLayer w0.8: CA26.2@183.025,139.077 185.454,139.077 v1(185.668,139.291) C20.2@185.668,140.678 ; v1(194.325,135.65) 194.35,135.625 C25.2@195.927,135.625 ; CA1.2@198.216,144.145 v1(198.216,145.669) v1@198.225,145.678 ; v1(201.722,137.75) C30.2@202.375,137.097 ; v1(210.85,156.6) 210.925,156.6 212.425,158.1 212.425,160.822 C12.2@214.128,162.525 ; v1(218.3,157.6) 218.927,158.227 C19.2@220.15,158.227 ; C11.2@221.522,155.45 223.148,153.824 C17.2@223.148,152.8 ; v1(222.375,145.9) 223.675,144.6 C32.2@223.675,144.575 ; v1(222.4,133.85) C31.2@223.725,135.175 ; v1(259.675,165.775) R9.2@260.553,165.775 260.553,164.903 v1(260.175,164.525)
  other v1: 184.575,139.05 222.35,154.5
AVCC: C9.1 C12.1 C18.1 C19.1 C20.1 CA26.1 J10.2 U3.1 U5.8 U18.2 | length 27.5
  TopLayer w0.3: C12.1@215.525,162.525 215.63,162.42 U5.8@215.63,158.987
  TopLayer w0.4: C9.1@209.137,138.829 209.645,138.321 U3.1@212.852,138.321
  TopLayer w0.6: v1(204.184,138.779) C18.1@206.216,138.779 ; C18.1@206.216,138.829 C9.1@209.137,138.829 ; C12.1@215.525,162.525 217.5,162.525 218.75,161.275 C19.1@220.15,161.275 220.15,162.825 v1(220.125,162.85)
  TopLayer w0.7: v1(183.45,143.8) 183.025,143.375 CA26.1@183.025,142.125 185.625,142.125 C20.1@185.637,142.113 ; 185.288,142.113 C20.1@185.637,142.113 ; U18.2@188.976,142.113 C20.1@185.713,142.113 ; C20.1@185.637,142.113 C20.1@185.713,142.113 ; C20.1@185.637,142.113 C20.1@185.675,142.075 C20.1@185.713,142.113
B_UART5: F11.2 GDT04.1 GDT06.1 J3.2 | length 22.6
  TopLayer w1: GDT06.1@232.001,141.775 230.85,141.775 229.121,140.046 F11.2@226.949,140.046 226.949,132.334 228.219,131.064 231.636,131.064 232.95,129.75 232.95,128.045 J3.2@233.172,127.823
CURA: F1.2 J4.1 | length 8.6
  TopLayer w1.2: F1.2@261,135.196 261,130.729 J4.1@263.906,127.823
CURB: F2.2 J5.2 | length 8
  TopLayer w1.2: F2.2@249.45,135.125 249.45,129.452 J5.2@251.079,127.823
DA_CS#: U2.1 U13.14 | length 8.6
  TopLayer w0.3: U2.1@253.111,149.619 254.95,151.458 254.95,154.546 255.27,154.866 U13.14@255.27,157.279
DA_DIN: U2.3 U13.12 | length 11
  TopLayer w0.3: U13.12@252.73,157.279 252.73,152.005 251.333,150.608 251.333,148.857 251.871,148.319 U2.3@253.111,148.319
DA_SCLK: U2.2 U13.13 | length 10.1
  TopLayer w0.3: U2.2@253.111,148.969 252.364,148.969 251.968,149.365 251.968,150.268 254,152.3 U13.13@254,157.279
DE485: U1.9 U12.5 U12.6 | length 35.1
  TopLayer w0.25: U1.9@208.217,173.99 208.217,172.883 v2(208.475,172.625) ; U12.6@233.76,166.775 233.76,168.31 234.3,168.85 235.03,168.85 ; v2(234.45,170.125) 235.03,169.545 235.03,168.85 ; U12.5@235.03,166.775 235.03,168.85
  BottomLayer w0.25: v2(208.475,172.625) 209.275,171.825 232.825,171.825 234.45,170.2 v2(234.45,170.125)
E\X\R\S\T\: ISP1.4 R69.2 U30.1 | length 56.4
  TopLayer w0.3: R69.2@198.344,158.944 198.344,159.456 197.7,160.1 186.825,160.1 185.85,161.075 185.85,177.775 187.175,179.1 190.425,179.1 196.4,185.075 203.395,185.075 ISP1.4@205.47,187.15
  TopLayer w0.4: R69.2@198.344,158.944 198.344,156.412 U30.1@198.346,156.41
EARTH: C01.2 GDT04.2 GDT05.1 J3.1 J4.3 J5.1 J6.1 pad.0 pad.4 pad.6 pad.7 ZD15.2 ZD16.1 | length 278
  TopLayer w0.8: J3.1@227.584,127.315 J3.1@228.092,127.823
  TopLayer w1: GDT04.2@231.902,135.828 234.525,135.828 GDT05.1@237.363,135.828
  TopLayer w1.2: ZD16.1@231.45,147.125 231.65,146.925 ZD15.2@237.95,146.925 ; v3@234.525,133.475 234.525,135.828 234.525,146.825 ; C01.2@299.025,127.475 299.025,127.43 C01.2@300.975,125.48
  BottomLayer w1.2: pad.6@184.15,108.585 181.483,111.252 181.483,183.007 pad.0@184.15,185.674 ; v3@234.567,133.367 232.899,131.699 228.6,131.699 228.092,131.191 J3.1@228.092,127.823 228.092,123.533 229.35,122.275 244.775,122.275 ; J5.1@245.999,127.823 245.999,123.499 244.775,122.275 ; J4.3@274.066,127.823 274.025,127.782 274.025,123.15 273.15,122.275 ; J6.1@281.686,127.823 281.686,123.361 280.6,122.275 273.15,122.275 ; pad.7@300.355,107.696 303.784,111.125 303.784,124.725 ; pad.4@300.442,185.522 303.784,182.18 303.784,124.725 ; C01.2@300.975,125.48 303.029,125.48 303.784,124.725 ; 244.775,122.275 273.15,122.275
  other v3: 234.55,133.475
GND: C3.2 C03.2 C4.2 C7.2 C13.2 C15.2 C16.2 C21.2 C23.2 C24.2 C27.2 C28.2 C42.2 C43.2 C44.2 C51.2 C56.2 C58.2 CA12.2 CA13.2 CA14.2 D9.1 D49.1 ISP1.6 JTAG1.4 JTAG1.6 JTAG1.8 JTAG1.10 JTAG1.12 JTAG1.14 JTAG1.16 JTAG1.18 JTAG1.20 LD1.K R8.2 R9.1 R11.2 R68.1 R73.1 R74.1 U1.5 U1.41 U4.1 U4.2 U4.3 U4.4 U4.7 U6.10 U6.11 U7.10 U7.11 U10.16 U12.1 U12.3 U12.9 U12.10 U13.2 U13.8 U14.1 U30.3 | length 179.3
  TopLayer w0.3: v1(210.185,172.593) 210.217,172.625 U1.5@210.217,173.99 ; U1.41@213.917,168.79 215.365,168.79 v1(215.5,168.925) ; v1(243.102,183.87) U7.10@243.102,184.579 ; LD1.K@258.734,185.945 v1(258.734,187.228) ; v1(264.568,184.166) U6.10@264.568,184.981
  TopLayer w0.4: v2(227.15,168.925) 227.8,169.575 v2(230.1,169.575)
  TopLayer w0.5: v1(192.975,178.225) 192.975,173.675 202.35,164.3 v2(203.925,164.3) ; v1(194.7,152.55) 194.725,152.575 C27.2@194.725,153.653 ; U30.3@198.346,153.87 199.93,153.87 v1(199.975,153.825) ; v1(201.55,158.975) R68.1@202.575,158.975 ; v1(219.6,178.375) 219.625,178.4 R73.1@220.728,178.4 ; R74.1@227.825,178.45 229.025,178.45 v1(229.05,178.475) ; R11.2@240.25,183.953 243.019,183.953 v1(243.102,183.87) ; U7.11@245.462,185.341 245.55,185.429 v1(245.55,187.3) ; v1(248.9,164.55) 248.92,164.57 U13.8@248.92,166.55 ; U13.2@256.54,166.55 256.54,164.56 v1(256.575,164.525) ; R8.2@261.76,184.478 262.072,184.166 v1(264.568,184.166) ; U6.11@267.11,185.981 v1(267.11,187.525) v1@267.11,187.562
  TopLayer w0.6: U4.4@196.342,176.784 197.809,176.784 198.475,177.45 v1(198.475,177.725) 198.475,178.225 ; U4.3@196.342,178.054 198.304,178.054 198.475,178.225 ; U4.2@196.342,179.324 198.326,179.324 v1@198.475,179.175 ; U4.1@196.342,180.594 197.756,180.594 198.475,179.875 v1@198.475,179.175 ; U4.7@201.93,179.324 v1(203.85,179.324) 205.359,179.324 C4.2@205.486,179.197 ; v1(204.422,182.322) C28.2@205.425,182.322 ; C16.2@209.169,181.102 v1(210.439,181.102) C15.2@211.582,181.102 ; v1@215.515,168.91 C3.2@218.059,168.91 ; U12.10@228.68,166.775 228.68,164.695 v1(228.9,164.475) 229.3,164.475 229.95,165.125 U12.9@229.95,166.775 ; v1(236.822,177.753) C58.2@237.875,177.753 237.926,177.753 v1@238.502,177.177 ; U12.3@237.57,166.775 237.57,165.378 238.332,164.616 239.348,164.616 240.11,165.378 U12.1@240.11,166.775 ; v1(255.05,170.25) 255.829,169.471 C56.2@256.413,169.471 ; v1(263.1,167.175) 261.95,166.025 R9.1@261.95,165.775 v1@263.225,165.775 ; 198.475,178.225 v1@198.475,179.175
  TopLayer w0.8: C44.2@232.622,170.275 234.298,171.951 CA14.2@234.298,173.075 v2@235.625,173.075 ; C43.2@240.222,170.25 v2(241.275,171.303) 241.798,171.826 CA13.2@241.798,173 ; v1(261.628,174.178) C51.2@261.628,175.175 v1(261.628,176.55) 261.628,177.22 C23.2@262.335,177.927 ; D49.1@275.186,180.487 275.186,183.226 C7.2@275.16,183.252 276.849,183.252 v1(277.522,183.925) C42.2@278.3,184.703
  TopLayer w1: v1@238.502,177.177 C13.2@240.575,177.177 ; C21.2@253.85,182.977 254.24,182.587 D9.1@254.24,180.164 v1@254.24,178.665 ; v1(261.625,171.35) U14.1@264,171.35 ; v1@269.923,174.323 C24.2@269.923,175.925
  TopLayer w1.2: CA12.2@286.727,185.075 v3@288.625,185.075
  TopLayer w1.5: U10.16@283.085,171.6 287.675,171.6 291.525,167.75 300.877,167.75 C03.2@303.2,165.427
  BottomLayer w0.3: v1(215.5,168.925) v2(227.15,168.925)
  BottomLayer w0.4: v2@230.075,169.6 231.425,168.25 v2(244.775,168.25) 252.025,168.25 254.025,170.25 v1(255.05,170.25)
  other v1: 216.6,164.275 238.925,164.55 193.05,164.875 263.25,165.8 226.525,166.45 209.7,167.6 269.9,174.3 213.2,176.15 238.475,177.15 214.675,177.625 254.225,178.65 198.45,179.275 254.275,181.525 275.15,181.975
  other v2: 206.725,167.15 235.65,173.05
  other v3: 288.65,185.05
GND_COM: C45.2 C46.1 CA15.2 CA16.2 R42.2 U12.11 U12.14 U12.16 U12.20 | length 37.8
  TopLayer w0.6: CA15.2@223.5,158.325 CA15.2@223.725,158.55 ; CA15.2@223.725,158.125 225.95,158.125 C45.2@226.225,158.4 227.403,158.4 U12.11@228.68,157.123 ; R42.2@231.575,152.147 232.49,153.062 U12.14@232.49,157.123 232.49,158.393 233.247,159.15 234.273,159.15 235.03,158.393 U12.16@235.03,157.123 ; U12.20@240.11,157.123 v1(241.595,157.123) C46.1@242.6,158.128 CA16.2@245.25,158.128
  BottomLayer w0.6: v1(227.625,158.125) 232.725,158.125 v1(233.775,159.175) 239.543,159.175 v1(241.595,157.123)
  other v1: 243.875,158.125 225.125,158.15
GUARD: J1.1 U3.4 | length 67.6
  TopLayer w0.254: 214.775,133.708 214.813,133.671 214.813,129.715 ccw(c215.392,127.823) 213.413,127.823 ccw(c215.392,127.823) 216.036,129.694 216.036,133.386 216.375,133.725 216.375,136.4 v2(216.075,136.7) 216.075,137.5
  TopLayer w0.3: J1.1@210.312,127.823 213.413,127.823 213.426,127.823 ; 214.775,133.708 214.525,133.958 214.525,136.389 214.802,136.666 U3.4@214.802,138.321 214.802,139.952 v2(215.25,140.4) 215.65,140.4 216.075,139.975 216.075,139.275
  BottomLayer w0.3: v2(215.25,140.4) 214.775,139.925 214.775,136.675 214.55,136.45 214.55,133.925 214.85,133.625 214.85,129.875 213.5,128.525 213.5,127 214.7,125.8 216.275,125.8 217.325,126.85 217.325,128.525 216.05,129.8 216.05,133.4 216.375,133.725 216.375,136.35 216.1,136.625 216.1,139.375
IAGND: C2.2 C5.2 C6.2 C52.2 C53.2 C54.2 C55.2 C57.2 CA22.2 CA23.2 CA25.2 D1.1 D2.1 R4.2 R5.2 R10.1 U2.7 U8.4 U9.4 U13.9 U13.15 U14.4 U15.2 | length 43.2
  TopLayer w0.4: U2.7@257.341,148.969 258.006,148.969 259.331,147.644 U8.4@260.858,147.644
  TopLayer w0.5: v1(248.075,155.628) 248.539,155.628 248.92,156.009 U13.9@248.92,157.279 ; 256.54,153.977 U13.15@256.54,157.279 U13.15@256.54,157.533
  TopLayer w0.6: v1(248,147.625) 248.038,147.587 C6.2@249.151,147.587 ; 252.331,140.361 252.331,141.563 D2.1@253.315,142.547 ; C55.2@261.35,156.522 262.976,158.148 CA25.2@264.15,158.148 ; R5.2@263.975,140.072 263.975,142.182 D1.1@264.24,142.447 ; C2.2@266.446,151.593 267.343,151.593 v1(267.375,151.625) ; C54.2@268.5,147.897 v1(268.5,149) ; U15.2@269.73,156.088 271.012,156.088 v1(271.025,156.075) ; v1@269.975,151.975 U9.4@271.09,151.975 ; CA22.2@275.023,142.875 275.023,141.252 v1(275.025,141.25) ; v3(277.25,138.875) R10.1@278.5,138.875 ; C53.2@277.747,155.325 277.747,154.278 v1@277.75,154.275 ; 277.825,137.6 278.5,138.275 R10.1@278.5,138.875 ; 277.825,140.125 278.5,139.45 R10.1@278.5,138.875 ; v1@277.897,159.453 C52.2@277.897,160.4
  TopLayer w0.635: C5.2@256.403,151.7 256.413,151.71 C57.2@256.413,153.556
  TopLayer w1: v3@261.35,160.975 261.35,162.625 262.455,163.73 U14.4@264.025,163.73 v3@264.025,161.125 ; v3(268.025,160.35) CA23.2@269.902,160.35
  other v1: 263.975,141.125 252.35,141.275 258.8,148.225 269.95,152 256.425,152.575 277.748,154.277 262.4,157.675 277.9,159.45
  other v3: 261.325,160.95 263.975,161.075
INP: C29.2 C32.1 R16.1 U3.5 | length 14.4
  TopLayer w0.3: R16.1@215.45,135.75 215.452,135.752 U3.5@215.452,138.321 215.452,139.573 v2(215.45,139.575) ; v2(219.55,140.975) 220.95,140.975 221.025,141.05 C29.2@221.025,141.375 C29.2@221.025,141.85
  TopLayer w0.8: C32.1@220.627,144.575 220.627,141.773 C29.2@221.025,141.375
  BottomLayer w0.3: v2(215.45,139.575) 216.525,140.65 219.325,140.65 219.65,140.975 v2(219.55,140.975)
IREF2.5V: C54.1 CA22.1 FB2.2 U9.6 | length 11
  TopLayer w0.6: C54.1@268.5,146.5 v3(268.5,145.375) 271,142.875 CA22.1@271.975,142.875 272.36,143.26 U9.6@272.36,146.387
  TopLayer w0.8: v1(247.85,144.775) 248.775,145.7 FB2.2@249.178,145.7
  other v1: 270.025,143.975
ISP_RXD: ISP1.3 U1.46 | length 30.4
  TopLayer w0.25: U1.46@213.917,171.29 215.415,171.29 216.15,172.025 v2(216.15,173.675)
  BottomLayer w0.25: ISP1.3@202.93,187.15 201.9,186.12 201.9,178.075 203.15,176.825 211.4,176.825 212.075,176.15 212.075,175.05 212.625,174.5 215.325,174.5 v2(216.15,173.675)
ISP_TXD: ISP1.2 U1.47 | length 29.5
  TopLayer w0.25: U1.47@213.917,171.79 214.99,171.79 215.425,172.225 v2(215.425,173.05)
  BottomLayer w0.25: ISP1.2@200.39,187.15 200.39,178.285 202.375,176.3 211.1,176.3 211.475,175.925 211.475,174.425 212.075,173.825 214.65,173.825 v2(215.425,173.05)
ISPEN: ISP1.1 R1.1 U1.4 | length 28.1
  TopLayer w0.25: U1.4@210.717,173.99 210.717,175.567 v2(210.725,175.575)
  TopLayer w0.5: R1.1@193.725,187.15 ISP1.1@197.85,187.15
  BottomLayer w0.25: ISP1.1@197.85,187.15 199.55,185.45 199.55,178.175 202.65,175.075 210.225,175.075 v2(210.725,175.575)
JTAG_RST: U1.35
JTAG_TDI: U1.32
JTAG_TDO: U1.34
JTAG_TMS: U1.33
LED_S1: LD3.K U1.37 | length 16.5
  TopLayer w0.25: U1.37@213.917,166.79 214.885,166.79 216.45,165.225 219.65,165.225 222.4,167.975 222.4,172.579 LD3.K@223.523,173.702
LED_S2: LD2.K U1.38 | length 14.7
  TopLayer w0.25: U1.38@213.917,167.29 215.21,167.29 216.75,165.75 219.125,165.75 221.366,167.991 LD2.K@221.366,173.663
MISO1: U1.30 U3.13 U5.9 | length 26.2
  TopLayer w0.25: U1.30@209.217,165.09 209.217,163.808 209.6,163.425 v2(210.925,163.425) ; v2(213.825,158.25) 214.4,157.675 214.9,157.675 215.13,157.905 U5.9@215.13,158.987 ; v2(214.8,145.675) 214.802,145.673 U3.13@214.802,144.721
  BottomLayer w0.25: v2(210.925,163.425) 213.425,160.925 213.425,158.65 v2(213.825,158.25) 213.825,155.125 214.8,154.15 v2(214.8,145.675)
MOSI1: U1.17 U3.16 U5.10 U13.5 | length 87.2
  TopLayer w0.25: v2(202.425,170.275) 202.44,170.29 U1.17@205.017,170.29 ; v2(214.275,160.7) 214.2,160.7 214.63,160.27 U5.10@214.63,158.987 ; v1(252.725,164.525) 252.725,166.545 U13.5@252.73,166.55
  TopLayer w0.3: v2(212.1,144.675) 212.146,144.721 U3.16@212.852,144.721
  BottomLayer w0.25: v2(202.425,170.275) 205.675,170.275 207.475,168.475 213.825,168.475 214.95,167.35 v2(216.525,167.35) ; v2(214.275,160.7) 214.275,165.1 v2(216.525,167.35) ; v1(252.725,164.525) 251.475,165.775 230.325,165.775 228.75,167.35 v2(216.525,167.35)
  BottomLayer w0.3: v2(212.1,144.675) 214.925,144.675 215.475,145.225 215.475,154.975 214.65,155.8 214.65,160.325 v2(214.275,160.7)
NetD6_A: LD2.A R17.1 | length 1.8
  TopLayer w0.3: R17.1@219.334,175.734 LD2.A@221.142,175.734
